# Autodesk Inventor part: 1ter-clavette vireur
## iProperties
Created: 2011-02
Part Number: 1ter-clavette vireur
Document SubType Name: Modeling
Designer: eric
Density: 1 g/cm^3
Author: eric
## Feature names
1. Base1
